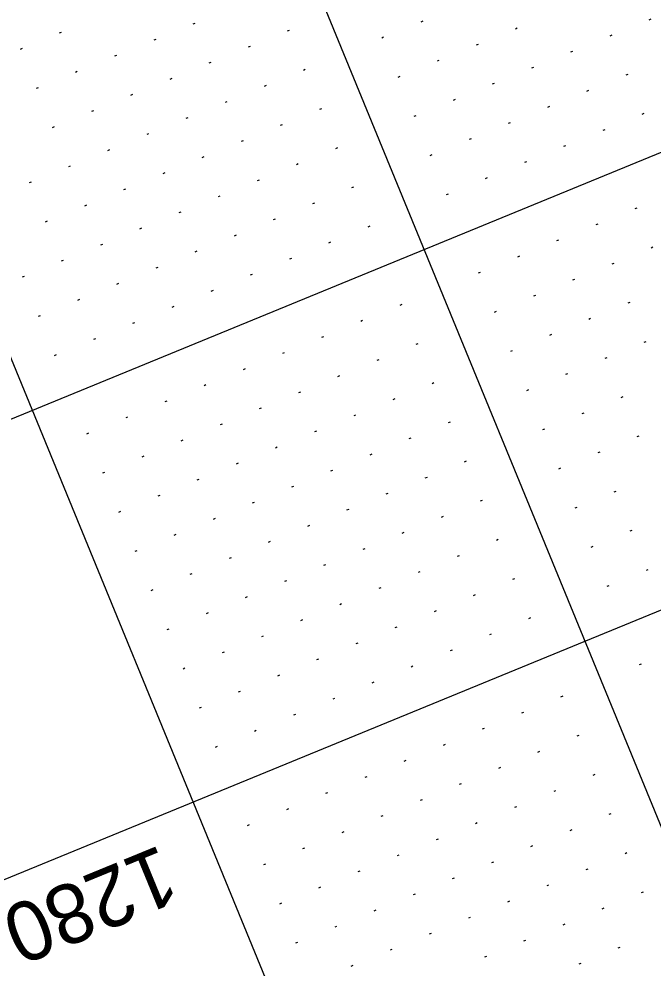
# Model space of a CAD drawing. Extents: x 2148770 to 2150891, y 142633 to 144465.
# Drawn here: x 2148940.4 to 2149015.3, y 143476.6 to 143588.8 of the extents above; entities that cross this region are included whole.
import ezdxf

# ---------------------------------------------------------------- set-up
doc = ezdxf.new("R2010")
doc.units = 0
for name, color, linetype in [('SHT_Plan_Profile_Sheet_Elev_Txt', 7, 'Continuous'), ('SHT_Profile_Grid_Major', 7, 'Continuous'), ('SHT_Profile_Grid_Minor', 7, 'Continuous'), ('SHT_Sheet_Border', 7, 'Continuous')]:
    doc.layers.add(name, color=color, linetype=linetype)

msp = doc.modelspace()

# ---------------------------------------------------------------- linework, layer by layer
at = {"layer": 'SHT_Profile_Grid_Major'}
for p, q in [((2150364.28, 144126.48), (2148907.29, 143528.3)), ((2150383.27, 144080.23), (2148926.28, 143482.05)), ((2148969.25, 143607.79), (2149121.17, 143237.76))]:
    msp.add_line(p, q, dxfattribs=at)
at = {"layer": 'SHT_Profile_Grid_Minor'}
for p, q in [((2148961.18, 143588.26), (2148960.95, 143588.16)), ((2148988.11, 143588.5), (2148987.88, 143588.41)), ((2149015.03, 143588.75), (2149014.8, 143588.65)), ((2148945.41, 143587.19), (2148945.18, 143587.09)), ((2148972.33, 143587.43), (2148972.1, 143587.34)), ((2148999.26, 143587.68), (2148999.03, 143587.58)), ((2149010.41, 143586.85), (2149010.18, 143586.75)), ((2148956.56, 143586.36), (2148956.33, 143586.27)), ((2148983.48, 143586.61), (2148983.25, 143586.51)), ((2148994.63, 143585.78), (2148994.4, 143585.68)), ((2148940.78, 143585.29), (2148940.55, 143585.19)), ((2148967.71, 143585.53), (2148967.48, 143585.44)), ((2149005.78, 143584.95), (2149005.55, 143584.86)), ((2148951.93, 143584.46), (2148951.7, 143584.37)), ((2148963.08, 143583.63), (2148962.85, 143583.54)), ((2148990.01, 143583.88), (2148989.78, 143583.78)), ((2148947.31, 143582.56), (2148947.08, 143582.47)), ((2148974.23, 143582.81), (2148974, 143582.71)), ((2149001.16, 143583.05), (2149000.92, 143582.96)), ((2148958.46, 143581.74), (2148958.22, 143581.64)), ((2148985.38, 143581.98), (2148985.15, 143581.88)), ((2148996.53, 143581.15), (2148996.3, 143581.06)), ((2149012.31, 143582.22), (2149012.07, 143582.13)), ((2148942.68, 143580.66), (2148942.45, 143580.57)), ((2148969.61, 143580.91), (2148969.37, 143580.81)), ((2149007.68, 143580.33), (2149007.45, 143580.23)), ((2148953.83, 143579.84), (2148953.6, 143579.74)), ((2148964.98, 143579.01), (2148964.75, 143578.91)), ((2148991.91, 143579.25), (2148991.67, 143579.16)), ((2148949.21, 143577.94), (2148948.97, 143577.84)), ((2148976.13, 143578.18), (2148975.9, 143578.09)), ((2149003.05, 143578.43), (2149002.82, 143578.33)), ((2148960.36, 143577.11), (2148960.12, 143577.02)), ((2148987.28, 143577.35), (2148987.05, 143577.26)), ((2149014.2, 143577.6), (2149013.97, 143577.5)), ((2148944.58, 143576.04), (2148944.35, 143575.94)), ((2148971.5, 143576.28), (2148971.27, 143576.19)), ((2148998.43, 143576.53), (2148998.2, 143576.43)), ((2149009.58, 143575.7), (2149009.35, 143575.6)), ((2148955.73, 143575.21), (2148955.5, 143575.12)), ((2148993.8, 143574.63), (2148993.57, 143574.53)), ((2148951.1, 143573.31), (2148950.87, 143573.22)), ((2148966.88, 143574.38), (2148966.65, 143574.29)), ((2148978.03, 143573.56), (2148977.8, 143573.46)), ((2149004.95, 143573.8), (2149004.72, 143573.71)), ((2148962.25, 143572.48), (2148962.02, 143572.39)), ((2148989.18, 143572.73), (2148988.95, 143572.63)), ((2148946.48, 143571.41), (2148946.25, 143571.32)), ((2148973.4, 143571.66), (2148973.17, 143571.56)), ((2149000.33, 143571.9), (2149000.1, 143571.81)), ((2148957.63, 143570.59), (2148957.4, 143570.49)), ((2148995.7, 143570), (2148995.47, 143569.91)), ((2148941.85, 143569.51), (2148941.62, 143569.42)), ((2148968.78, 143569.76), (2148968.55, 143569.66)), ((2148979.93, 143568.93), (2148979.7, 143568.84)), ((2148953, 143568.69), (2148952.77, 143568.59)), ((2148964.15, 143567.86), (2148963.92, 143567.76)), ((2148991.08, 143568.1), (2148990.85, 143568.01)), ((2148948.38, 143566.79), (2148948.15, 143566.69)), ((2148975.3, 143567.03), (2148975.07, 143566.94)), ((2148959.53, 143565.96), (2148959.3, 143565.87)), ((2149013.38, 143566.45), (2149013.15, 143566.35)), ((2148943.75, 143564.89), (2148943.52, 143564.79)), ((2148970.68, 143565.13), (2148970.45, 143565.04)), ((2149008.75, 143564.55), (2149008.52, 143564.46)), ((2148954.9, 143564.06), (2148954.67, 143563.97)), ((2148966.05, 143563.23), (2148965.82, 143563.14)), ((2148981.83, 143564.31), (2148981.6, 143564.21)), ((2148950.28, 143562.16), (2148950.05, 143562.07)), ((2148977.2, 143562.41), (2148976.97, 143562.31)), ((2149004.13, 143562.65), (2149003.9, 143562.56)), ((2148961.43, 143561.34), (2148961.2, 143561.24)), ((2149015.28, 143561.82), (2149015.05, 143561.73)), ((2148945.65, 143560.26), (2148945.42, 143560.17)), ((2148972.58, 143560.51), (2148972.35, 143560.41)), ((2148999.5, 143560.75), (2148999.27, 143560.66)), ((2149010.65, 143559.92), (2149010.42, 143559.83)), ((2148956.8, 143559.44), (2148956.57, 143559.34)), ((2148994.88, 143558.85), (2148994.64, 143558.76)), ((2148941.03, 143558.36), (2148940.8, 143558.27)), ((2148967.95, 143558.61), (2148967.72, 143558.51)), ((2149006.03, 143558.03), (2149005.79, 143557.93)), ((2148952.18, 143557.54), (2148951.94, 143557.44)), ((2148963.33, 143556.71), (2148963.09, 143556.61)), ((2148947.55, 143555.64), (2148947.32, 143555.54)), ((2149001.4, 143556.13), (2149001.17, 143556.03)), ((2148958.7, 143554.81), (2148958.47, 143554.72)), ((2148985.63, 143555.05), (2148985.39, 143554.96)), ((2149012.55, 143555.3), (2149012.32, 143555.2)), ((2148942.93, 143553.74), (2148942.69, 143553.64)), ((2148981, 143553.16), (2148980.77, 143553.06)), ((2148996.77, 143554.23), (2148996.54, 143554.13)), ((2149007.92, 143553.4), (2149007.69, 143553.31)), ((2148954.08, 143552.91), (2148953.84, 143552.82)), ((2148949.45, 143551.01), (2148949.22, 143550.92)), ((2148976.37, 143551.26), (2148976.14, 143551.16)), ((2149003.3, 143551.5), (2149003.07, 143551.41)), ((2148987.52, 143550.43), (2148987.29, 143550.33)), ((2149014.45, 143550.67), (2149014.22, 143550.58)), ((2148944.82, 143549.11), (2148944.59, 143549.02)), ((2148971.75, 143549.36), (2148971.52, 143549.26)), ((2148998.67, 143549.6), (2148998.44, 143549.51)), ((2149009.82, 143548.78), (2149009.59, 143548.68)), ((2148982.9, 143548.53), (2148982.67, 143548.44)), ((2148967.12, 143547.46), (2148966.89, 143547.36)), ((2148978.27, 143546.63), (2148978.04, 143546.54)), ((2149005.2, 143546.88), (2149004.97, 143546.78)), ((2148962.5, 143545.56), (2148962.27, 143545.47)), ((2148989.42, 143545.8), (2148989.19, 143545.71)), ((2148973.65, 143544.73), (2148973.42, 143544.64)), ((2149000.57, 143544.98), (2149000.34, 143544.88)), ((2149011.72, 143544.15), (2149011.49, 143544.05)), ((2148957.87, 143543.66), (2148957.64, 143543.57)), ((2148984.8, 143543.91), (2148984.57, 143543.81)), ((2148969.02, 143542.83), (2148968.79, 143542.74)), ((2148980.17, 143542.01), (2148979.94, 143541.91)), ((2149007.1, 143542.25), (2149006.87, 143542.16)), ((2148953.25, 143541.76), (2148953.02, 143541.67)), ((2148964.4, 143540.93), (2148964.17, 143540.84)), ((2148991.32, 143541.18), (2148991.09, 143541.08)), ((2148948.62, 143539.86), (2148948.39, 143539.77)), ((2148975.55, 143540.11), (2148975.32, 143540.01)), ((2149002.47, 143540.35), (2149002.24, 143540.26)), ((2148959.77, 143539.04), (2148959.54, 143538.94)), ((2148986.7, 143539.28), (2148986.47, 143539.19)), ((2149013.62, 143539.52), (2149013.39, 143539.43)), ((2148970.92, 143538.21), (2148970.69, 143538.11)), ((2149009, 143537.63), (2149008.77, 143537.53)), ((2148955.15, 143537.14), (2148954.92, 143537.04)), ((2148966.3, 143536.31), (2148966.07, 143536.21)), ((2148982.07, 143537.38), (2148981.84, 143537.29)), ((2148993.22, 143536.55), (2148992.99, 143536.46)), ((2148950.52, 143535.24), (2148950.29, 143535.14)), ((2148977.45, 143535.48), (2148977.21, 143535.39)), ((2149004.37, 143535.73), (2149004.14, 143535.63)), ((2148961.67, 143534.41), (2148961.44, 143534.32)), ((2148988.6, 143534.65), (2148988.36, 143534.56)), ((2148972.82, 143533.58), (2148972.59, 143533.49)), ((2149010.9, 143533), (2149010.66, 143532.91)), ((2148957.05, 143532.51), (2148956.81, 143532.42)), ((2148983.97, 143532.76), (2148983.74, 143532.66)), ((2148995.12, 143531.93), (2148994.89, 143531.83)), ((2148968.2, 143531.68), (2148967.96, 143531.59)), ((2148979.35, 143530.86), (2148979.11, 143530.76)), ((2149006.27, 143531.1), (2149006.04, 143531.01)), ((2148952.42, 143530.61), (2148952.19, 143530.52)), ((2148963.57, 143529.78), (2148963.34, 143529.69)), ((2148990.49, 143530.03), (2148990.26, 143529.93)), ((2148974.72, 143528.96), (2148974.49, 143528.86)), ((2148958.94, 143527.89), (2148958.71, 143527.79)), ((2148985.87, 143528.13), (2148985.64, 143528.04)), ((2149012.79, 143528.37), (2149012.56, 143528.28)), ((2148970.09, 143527.06), (2148969.86, 143526.96)), ((2148981.24, 143526.23), (2148981.01, 143526.14)), ((2148997.02, 143527.3), (2148996.79, 143527.21)), ((2149008.17, 143526.48), (2149007.94, 143526.38)), ((2148954.32, 143525.99), (2148954.09, 143525.89)), ((2148965.47, 143525.16), (2148965.24, 143525.06)), ((2148992.39, 143525.4), (2148992.16, 143525.31)), ((2148976.62, 143524.33), (2148976.39, 143524.24)), ((2148960.84, 143523.26), (2148960.61, 143523.17)), ((2148987.77, 143523.5), (2148987.54, 143523.41)), ((2149014.69, 143523.75), (2149014.46, 143523.65)), ((2148971.99, 143522.43), (2148971.76, 143522.34)), ((2148998.92, 143522.68), (2148998.69, 143522.58)), ((2149010.07, 143521.85), (2149009.84, 143521.76)), ((2148956.22, 143521.36), (2148955.99, 143521.27)), ((2148983.14, 143521.61), (2148982.91, 143521.51)), ((2148994.29, 143520.78), (2148994.06, 143520.68)), ((2148967.37, 143520.53), (2148967.14, 143520.44)), ((2148978.52, 143519.71), (2148978.29, 143519.61)), ((2148962.74, 143518.64), (2148962.51, 143518.54)), ((2148989.67, 143518.88), (2148989.44, 143518.78)), ((2148973.89, 143517.81), (2148973.66, 143517.71)), ((2149000.82, 143518.05), (2149000.59, 143517.96)), ((2148958.12, 143516.74), (2148957.89, 143516.64)), ((2148985.04, 143516.98), (2148984.81, 143516.89)), ((2148996.19, 143516.15), (2148995.96, 143516.06)), ((2148969.27, 143515.91), (2148969.04, 143515.81)), ((2148980.42, 143515.08), (2148980.19, 143514.99)), ((2148964.64, 143514.01), (2148964.41, 143513.92)), ((2148991.57, 143514.25), (2148991.34, 143514.16)), ((2148975.79, 143513.18), (2148975.56, 143513.09)), ((2148960.02, 143512.11), (2148959.79, 143512.02)), ((2148986.94, 143512.36), (2148986.71, 143512.26)), ((2149013.87, 143512.6), (2149013.63, 143512.5)), ((2148971.17, 143511.28), (2148970.93, 143511.19)), ((2148966.54, 143509.38), (2148966.31, 143509.29)), ((2148982.32, 143510.46), (2148982.08, 143510.36)), ((2148977.69, 143508.56), (2148977.46, 143508.46)), ((2149004.62, 143508.8), (2149004.38, 143508.71)), ((2148961.92, 143507.49), (2148961.68, 143507.39)), ((2148973.07, 143506.66), (2148972.83, 143506.56)), ((2148999.99, 143506.9), (2148999.76, 143506.81)), ((2148995.36, 143505), (2148995.13, 143504.91)), ((2148968.44, 143504.76), (2148968.21, 143504.66)), ((2149006.51, 143504.18), (2149006.28, 143504.08)), ((2148963.81, 143502.86), (2148963.58, 143502.77)), ((2148990.74, 143503.1), (2148990.51, 143503.01)), ((2149001.89, 143502.28), (2149001.66, 143502.18)), ((2148986.11, 143501.21), (2148985.88, 143501.11)), ((2148981.49, 143499.31), (2148981.26, 143499.21)), ((2148997.26, 143500.38), (2148997.03, 143500.28)), ((2149008.41, 143499.55), (2149008.18, 143499.46)), ((2148992.64, 143498.48), (2148992.41, 143498.38)), ((2148976.86, 143497.41), (2148976.63, 143497.31)), ((2149003.79, 143497.65), (2149003.56, 143497.56)), ((2148988.01, 143496.58), (2148987.78, 143496.49)), ((2148972.24, 143495.51), (2148972.01, 143495.41)), ((2148999.16, 143495.75), (2148998.93, 143495.66)), ((2149010.31, 143494.93), (2149010.08, 143494.83)), ((2148983.39, 143494.68), (2148983.16, 143494.59)), ((2148994.54, 143493.85), (2148994.31, 143493.76)), ((2148967.61, 143493.61), (2148967.38, 143493.51)), ((2148978.76, 143492.78), (2148978.53, 143492.69)), ((2149005.69, 143493.03), (2149005.46, 143492.93)), ((2148989.91, 143491.95), (2148989.68, 143491.86)), ((2148974.14, 143490.88), (2148973.91, 143490.79)), ((2149001.06, 143491.13), (2149000.83, 143491.03)), ((2149012.21, 143490.3), (2149011.98, 143490.21)), ((2148985.29, 143490.06), (2148985.06, 143489.96)), ((2148996.44, 143489.23), (2148996.2, 143489.13)), ((2148969.51, 143488.98), (2148969.28, 143488.89)), ((2148980.66, 143488.16), (2148980.43, 143488.06)), ((2149007.59, 143488.4), (2149007.35, 143488.31)), ((2148991.81, 143487.33), (2148991.58, 143487.23)), ((2148976.04, 143486.26), (2148975.8, 143486.16)), ((2149002.96, 143486.5), (2149002.73, 143486.41)), ((2148987.19, 143485.43), (2148986.95, 143485.34)), ((2149014.11, 143485.67), (2149013.88, 143485.58)), ((2148971.41, 143484.36), (2148971.18, 143484.26)), ((2148998.34, 143484.6), (2148998.1, 143484.51)), ((2149009.48, 143483.78), (2149009.25, 143483.68)), ((2148982.56, 143483.53), (2148982.33, 143483.44)), ((2148993.71, 143482.7), (2148993.48, 143482.61)), ((2148977.93, 143481.63), (2148977.7, 143481.54)), ((2149004.86, 143481.88), (2149004.63, 143481.78)), ((2148989.08, 143480.81), (2148988.85, 143480.71)), ((2148973.31, 143479.73), (2148973.08, 143479.64)), ((2149000.23, 143479.98), (2149000, 143479.88)), ((2149011.38, 143479.15), (2149011.15, 143479.06)), ((2148984.46, 143478.91), (2148984.23, 143478.81)), ((2148995.61, 143478.08), (2148995.38, 143477.98)), ((2148979.83, 143477.01), (2148979.6, 143476.91)), ((2149006.76, 143477.25), (2149006.53, 143477.16))]:
    msp.add_line(p, q, dxfattribs=at)
at = {"layer": 'SHT_Sheet_Border'}
msp.add_line((2148894.51, 143658.18), (2149074.91, 143218.77), dxfattribs=at)

# ---------------------------------------------------------------- texts
at = {"layer": 'SHT_Plan_Profile_Sheet_Elev_Txt'}
msp.add_text('1280', height=7, rotation=202.3213, dxfattribs=at).set_placement((2148957.18, 143491.32))

doc.saveas('drawing.dxf')
